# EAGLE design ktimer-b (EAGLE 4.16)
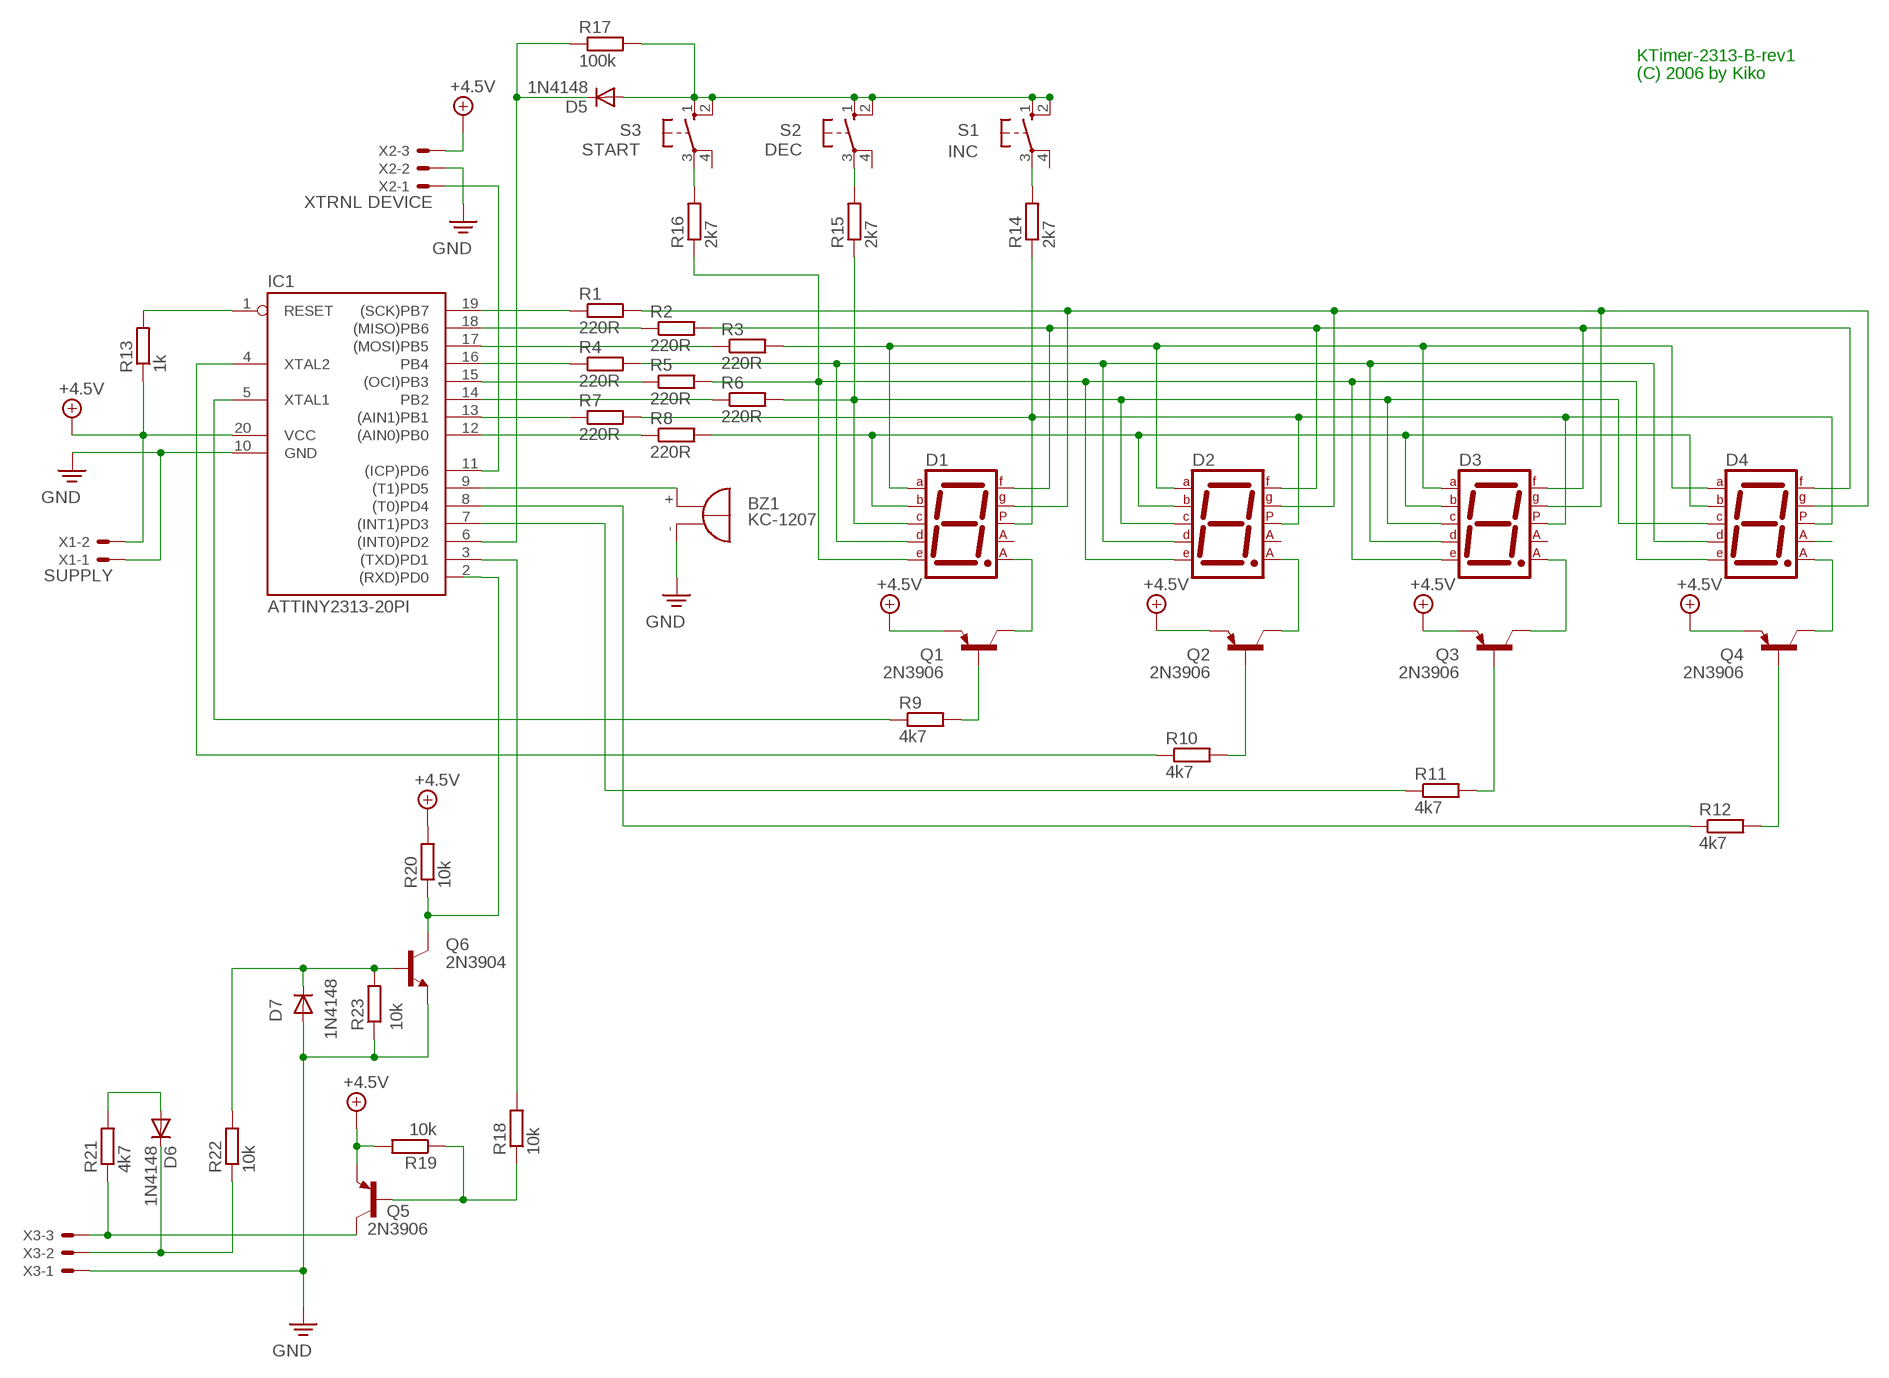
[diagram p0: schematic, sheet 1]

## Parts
BZ1  KC-1207  F/QMBIII  [F/QMBIII]
D1  7SEG-CA  [7SEG-13]
D2  7SEG-CA  [7SEG-13]
D3  7SEG-CA  [7SEG-13]
D4  7SEG-CA  [7SEG-13]
D5  1N4148  BAT81  [DO34-7]
D6  1N4148  BAT81  [DO34-7]
D7  1N4148  BAT81  [DO34-7]
IC1  ATTINY2313-20PI  AT90S2313P  [DIL20]
Q1  2N3906  [TO92]
Q2  2N3906  [TO92]
Q3  2N3906  [TO92]
Q4  2N3906  [TO92]
Q5  2N3906  [TO92]
Q6  2N3904  [TO92]
R1  220R  R-EU_0204/7  [0204/7]
R2  220R  R-EU_0204/7  [0204/7]
R3  220R  R-EU_0204/7  [0204/7]
R4  220R  R-EU_0204/7  [0204/7]
R5  220R  R-EU_0204/7  [0204/7]
R6  220R  R-EU_0204/7  [0204/7]
R7  220R  R-EU_0204/7  [0204/7]
R8  220R  R-EU_0204/7  [0204/7]
R9  4k7  R-EU_0204/7  [0204/7]
R10  4k7  R-EU_0204/7  [0204/7]
R11  4k7  R-EU_0204/7  [0204/7]
R12  4k7  R-EU_0204/7  [0204/7]
R13  1k  R-EU_0204/7  [0204/7]
R14  2k7  R-EU_0204/7  [0204/7]
R15  2k7  R-EU_0204/7  [0204/7]
R16  2k7  R-EU_0204/7  [0204/7]
R17  100k  R-EU_0204/7  [0204/7]
R18  10k  R-EU_0207/2V  [0207/2V]
R19  10k  R-EU_0207/2V  [0207/2V]
R20  10k  R-EU_0207/2V  [0207/2V]
R21  4k7  R-EU_0207/2V  [0207/2V]
R22  10k  R-EU_0207/2V  [0207/2V]
R23  10k  R-EU_0207/2V  [0207/2V]
S1  INC  40-XX  [B3F-40XX]
S2  DEC  40-XX  [B3F-40XX]
S3  START  40-XX  [B3F-40XX]
X1  SUPPLY  22-23-2021  [22-23-2021]
X2  XTRNL DEVICE  22-23-2031  [22-23-2031]
X3  22-23-2031  [22-23-2031]

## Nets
+5V: IC1.20(VCC) Q1.3(E) Q2.3(E) Q3.3(E) Q4.3(E) Q5.3(E) R13.1 R19.2 R20.2 X1.2 X2.3 ; supply symbol labelled +4.5V
GND: BZ1.-(+) IC1.10(GND) X1.1 X2.2
N$1: D1.10(G) D2.10(G) D3.10(G) D4.10(G) R1.2
N$2: D1.9(F) D2.9(F) D3.9(F) D4.9(F) R2.2
N$3: D1.7(A) D2.7(A) D3.7(A) D4.7(A) R3.2
N$4: D1.2(D) D2.2(D) D3.2(D) D4.2(D) R4.2
N$5: D1.1(E) D2.1(E) D3.1(E) D4.1(E) R5.2 R16.1
N$6: D1.4(C) D2.4(C) D3.4(C) D4.4(C) R6.2 R15.1
N$7: D1.5(DP) D2.5(DP) D3.5(DP) D4.5(DP) R7.2 R14.1
N$8: D1.6(B) D2.6(B) D3.6(B) D4.6(B) R8.2
N$9: IC1.19((SCK)PB7) R1.1
N$10: IC1.18((MISO)PB6) R2.1
N$11: IC1.17((MOSI)PB5) R3.1
N$12: IC1.16(PB4) R4.1
N$13: IC1.15((OCI)PB3) R5.1
N$14: IC1.14(PB2) R6.1
N$15: IC1.13((AIN1)PB1) R7.1
N$16: IC1.12((AIN0)PB0) R8.1
N$17: Q1.2(B) R9.2
N$18: IC1.5(XTAL1) R9.1
N$19: D1.8(CA2) Q1.1(C)
N$20: D2.8(CA2) Q2.1(C)
N$21: D3.8(CA2) Q3.1(C)
N$22: D4.3(CA1)
N$23: Q2.2(B) R10.2
N$24: IC1.4(XTAL2) R10.1
N$25: Q3.2(B) R11.2
N$26: Q4.2(B) R12.2
N$27: IC1.7((INT1)PD3) R11.1
N$28: IC1.8((T0)PD4) R12.1
N$29: IC1.1(RESET) R13.2
N$30: BZ1.+(-) IC1.9((T1)PD5)
N$31: R14.2 S1.3(P)
N$32: R15.2 S2.3(P)
N$33: R16.2 S3.3(P)
N$34: D5.C IC1.6((INT0)PD2) R17.1
N$35: D5.A R17.2 S1.1(S) S1.2(S1) S2.1(S) S2.2(S1) S3.1(S) S3.2(S1)
N$36: D4.8(CA2) Q4.1(C)
N$37: IC1.11((ICP)PD6) X2.1
N$38: IC1.3((TXD)PD1) R18.2
N$39: Q5.2(B) R18.1 R19.1
N$42: Q5.1(C) R21.1 X3.3
N$43: IC1.2((RXD)PD0) Q6.1(C) R20.1
N$44: D6.C R22.1 X3.2
N$45: D7.C Q6.2(B) R22.2 R23.2
N$46: D6.A R21.2
PE: D7.A Q6.3(E) R23.1 X3.1 ; supply symbol labelled GND
Unconnected: D1.3(CA1) D2.3(CA1) D3.3(CA1) S1.4(P1) S2.4(P1) S3.4(P1)

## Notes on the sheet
- KTimer-2313-B-rev1
- (C) 2006 by Kiko

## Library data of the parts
BZ1 = buzzer:F/QMBIII: BUZZER
D1-D4 = special:7SEG-CA: 7-segment DISPLAY single anode, 13 mm
D5-D7 = diode:BAT81: DIODE
IC1 = atmel2:AT90S2313: MICROCONTROLLER 2 Kbytes FLASH 128 bytes SRAM 128 bytes EEPROM UART
Q1-Q5 = transistor-pnp:2N3906: PNP Transistor
Q6 = transistor-npn:2N3904: NPN Transistor
R1-R23 = rcl:R-EU_: RESISTOR, European symbol
S1-S3 = switch-omron:40-XX: OMRON SWITCH
X1 = con-molex:22-23-2021: .100" (2.54mm) Center Header - 2 Pin
X2 X3 = con-molex:22-23-2031: .100" (2.54mm) Center Header - 3 Pin

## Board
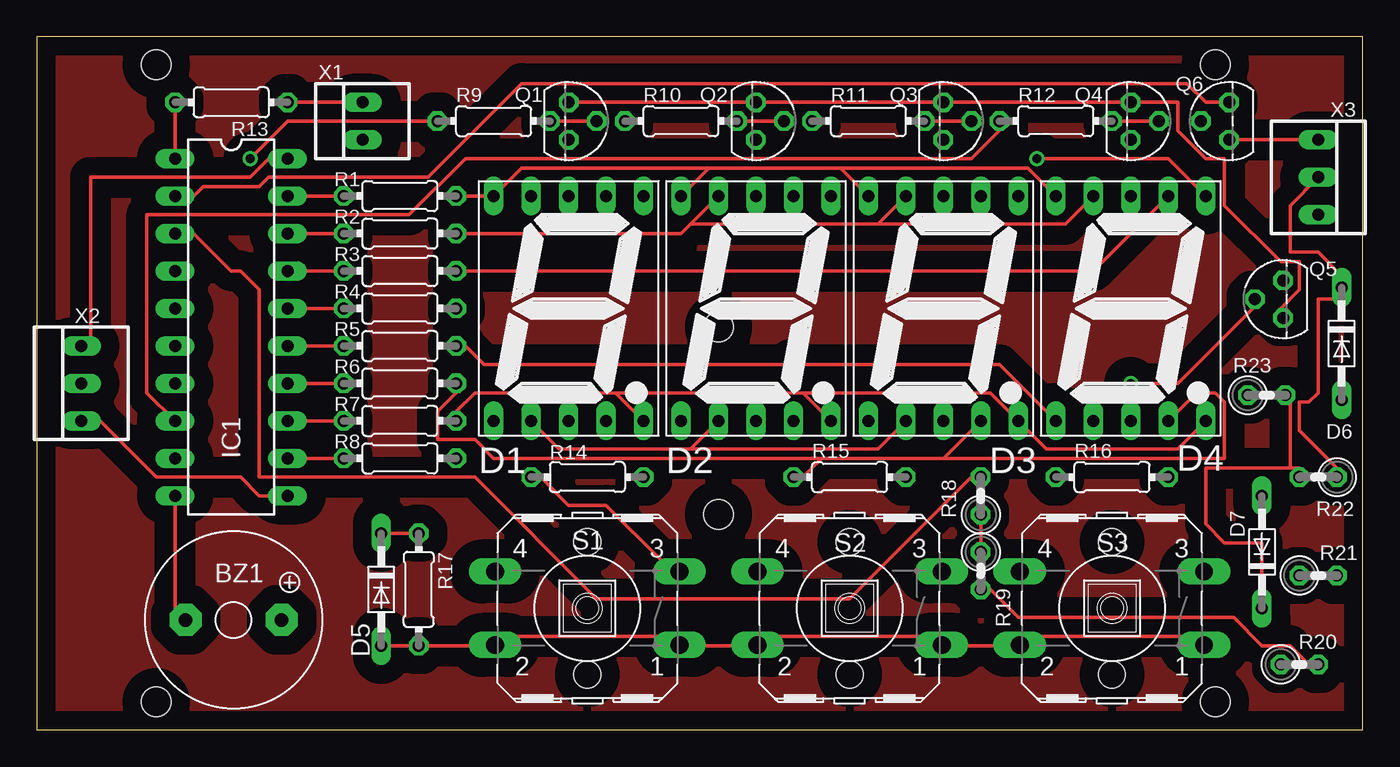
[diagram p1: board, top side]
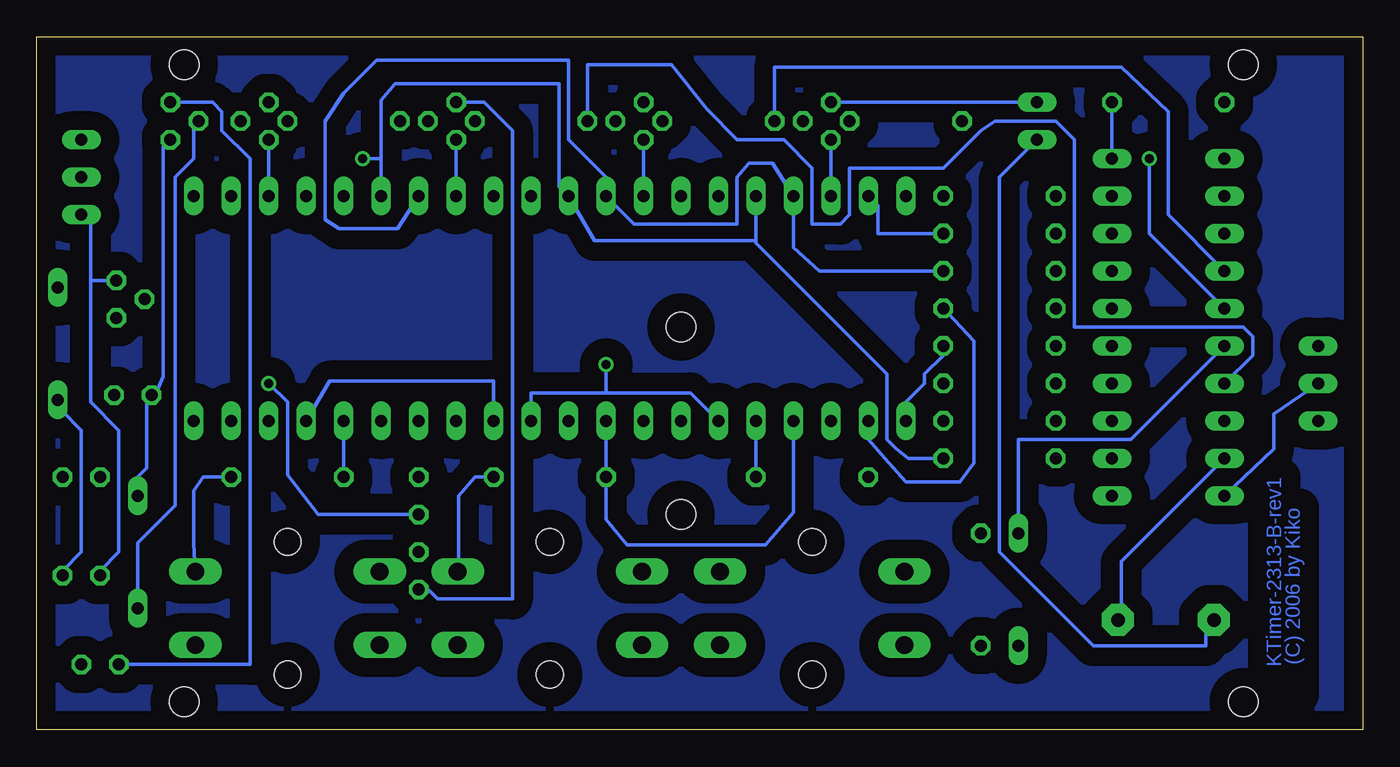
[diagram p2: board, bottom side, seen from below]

Size 89.84 x 46.98 mm. Coordinates in mm from the lower left corner, seen from the top.
Outline: 0,0 89.84,0 89.84,46.98 0,46.98 0,0
Copper layers (1*16): Top 0.035mm / dielectric 1.5mm / Bottom 0.035mm
Design rules "default": minimum track width 10mil, minimum drill 24mil, track to track 8mil, track to pad 8mil, pad to pad 8mil, via to via 8mil, smd to smd 8mil, copper to edge 40mil, drill to drill 8mil, minimum pad ring 10mil, minimum via ring 8mil, stop-mask expansion 4mil, vias tented up to drill 0mil, thermal gap 10mil
Holes 2 mm at 8.09,45.08 8.09,1.9 79.84,1.9 79.84,45.08 46.19,14.6 46.19,27.3

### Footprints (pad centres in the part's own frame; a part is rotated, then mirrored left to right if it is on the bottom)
F/QMBIII = drill 0.914 pad 2.159 octagon: + 3.251,0; - -3.251,0
7SEG-13 = drill 0.813 long: 1 -5.08,-7.62; 2 -2.54,-7.62; 3 0,-7.62; 4 2.54,-7.62; 5 5.08,-7.62; 6 5.08,7.62; 7 2.54,7.62; 8 0,7.62; 9 -2.54,7.62; 10 -5.08,7.62
DO34-7 = drill 0.813 long: A 3.81,0; C -3.81,0
DIL20 = drill 0.813 long: 1 -11.43,-3.81; 2 -8.89,-3.81; 3 -6.35,-3.81; 4 -3.81,-3.81; 5 -1.27,-3.81; 6 1.27,-3.81; 7 3.81,-3.81; 8 6.35,-3.81; 9 8.89,-3.81; 10 11.43,-3.81; 11 11.43,3.81; 12 8.89,3.81; 13 6.35,3.81; 14 3.81,3.81; 15 1.27,3.81; 16 -1.27,3.81; 17 -3.81,3.81; 18 -6.35,3.81; 19 -8.89,3.81; 20 -11.43,3.81
TO92 = drill 0.813 octagon: 1 1.27,0; 2 0,1.905; 3 -1.27,0
0204/7 = drill 0.813 octagon: 1 -3.81,0; 2 3.81,0
0207/2V = drill 0.813 octagon: 1 -1.27,0; 2 1.27,0
B3F-40XX = drill 1.194 long: 1 -6.248,2.489; 2 6.248,2.489; 3 -6.248,-2.489; 4 6.248,-2.489 | hole 1.803: 0,-4.496; 0,4.496
22-23-2021 = drill 0.813 long: 1 -1.27,0; 2 1.27,0
22-23-2031 = drill 0.813 long: 1 -2.54,0; 2 0,0; 3 2.54,0

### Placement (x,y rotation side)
BZ1  13.33,7.46 0 top
D1  36.03,28.57 0 top
D2  48.73,28.57 0 top
D3  61.43,28.57 0 top
D4  74.13,28.57 0 top
D5  23.33,9.52 270 top
D6  88.42,26.19 270 top
D7  83.02,12.06 90 top
IC1  13.17,27.3 270 top
Q1  36.03,41.27 270 top
Q2  48.73,41.27 270 top
Q3  61.43,41.27 270 top
Q4  74.13,41.27 270 top
Q5  84.45,29.2 90 top
Q6  80.8,41.27 90 top
R1  24.6,36.19 0 top
R2  24.6,33.65 0 top
R3  24.6,31.11 0 top
R4  24.6,28.57 0 top
R5  24.6,26.03 0 top
R6  24.6,23.49 0 top
R7  24.6,20.95 0 top
R8  24.6,18.41 0 top
R9  30.95,41.27 0 top
R10  43.65,41.27 0 top
R11  56.35,41.27 0 top
R12  69.05,41.27 0 top
R13  13.17,42.54 180 top
R14  37.3,17.14 180 top
R15  55.08,17.14 0 top
R16  72.86,17.14 0 top
R17  25.87,9.52 270 top
R18  63.97,15.87 90 top
R19  63.97,10.79 270 top
R20  85.56,4.44 0 top
R21  86.83,10.47 0 top
R22  86.83,17.14 180 top
R23  83.34,22.7 0 top
S1  37.3,8.25 180 top
S2  55.08,8.25 180 top
S3  72.86,8.25 180 top
X1  22.06,41.27 90 top
X2  3.01,23.49 90 top
X3  SERIAL  [22-23-2031]  86.83,37.46 270 top

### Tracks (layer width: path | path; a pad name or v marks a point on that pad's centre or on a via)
+5V
  Top 0.254: X2.3 3.65,26.66 3.65,37.46 14.44,37.46 15.71,38.73 IC1.20 | R13.1 X1.2 | R19.2 64.6,9.52 66.51,7.62 81.11,7.62 83.02,5.71 84.92,5.71 86.19,4.44 R20.2 | Q1.3 Q2.3 Q3.3 Q4.3 77.3,42.54 77.3,40.63 79.21,38.73 80.48,38.73 80.48,35.55 84.29,31.74 85.56,31.74 85.56,29.84 84.29,28.57 Q5.3
  Bottom 0.254: IC1.20 R13.1 | R19.2 63.33,9.52 62.7,8.88 57.62,8.88 57.62,40.63 59.53,42.54 Q3.3 | X1.2 Q1.3
GND
  Top 0.254: IC1.10 9.36,8.25 BZ1.-
  Bottom 0.254: X2.2 6.03,21.43 6.03,19.04 IC1.10 | X1.1 24.6,37.46 24.6,12.06 18.25,5.71 10.63,5.71 10.63,6.98 BZ1.-
N$1
  Top 0.254: R1.2 D1.10 32.86,38.09 45.56,38.09 | 45.56,38.09 54.44,38.09 | 45.56,38.09 D2.10 | 54.44,38.09 D3.10 | 54.44,38.09 67.14,38.09 D4.10
N$2
  Top 0.254: 44.28,34.28 43.65,33.65 R2.2 | 44.28,34.28 D2.9 | 44.28,34.28 56.98,34.28 | 56.98,34.28 D3.9 | 56.98,34.28 69.69,34.28 D4.9
  Bottom 0.254: R2.2 32.86,33.65 32.86,35.55 D1.9
N$3
  Top 0.254: D4.7 71.59,31.11 R3.2
  Bottom 0.254: R3.2 36.82,31.11 38.57,32.7 D1.7 40,38.41 41.59,38.41 42.38,37.46 42.38,34.28 49.36,34.28 D2.7 51.27,37.46 53.81,40 53.81,45.4 66.83,45.4 69.05,43.17 70.32,41.27 70.32,34.6 69.37,33.97 65.4,33.97 D3.7
N$4
  Top 0.254: 44.28,19.04 35.39,19.04 D1.2 | 44.28,19.04 D2.2 | 44.28,19.04 56.98,19.04 D3.2
  Bottom 0.254: R4.2 28.09,28.25 26.35,26.35 26.35,18.09 27.3,16.82 30.95,16.82 32.38,18.41 33.49,19.68 D1.2 | D4.2 70,23.65 58.89,23.65 D3.2
N$5  (via drill 0.61)
  Top 0.254: D4.1 65.24,24.76 v51.27,24.76 30.32,24.76 29.04,26.03 R5.2
  Bottom 0.254: 51.27,22.86 56.35,22.86 D3.1 | 51.27,22.86 45.56,22.86 D2.1 | D4.1 R16.1 | D1.1 30.95,22.22 29.68,23.49 29.68,24.12 28.41,25.39 R5.2 | v51.27,24.76 51.27,22.86
N$6
  Top 0.254: 53.17,18.41 61.43,18.41 | 53.17,18.41 51.91,17.14 R15.1 | 61.43,18.41 D3.4 | 61.43,18.41 80.48,18.41 80.48,22.22 79.84,22.86 78.58,22.86 D4.4 | 53.17,18.41 30.95,18.41 29.68,19.68 27.14,19.68 27.14,21.59 28.41,22.86 R6.2
  Bottom 0.254: D2.4 R15.1 51.27,16.35 51.27,14.28 49.84,12.54 40.47,12.54 38.57,14.76 38.57,19.68 D1.4
N$7
  Top 0.254: 39.2,22.86 29.68,22.86 28.41,21.59 R7.2 | 39.2,22.86 D1.5 | 39.2,22.86 51.91,22.86 | 51.91,22.86 D2.5 | 51.91,22.86 64.6,22.86 D3.5 68.41,19.04 77.3,19.04 D4.5
  Bottom 0.254: D1.5 R14.1
N$8  (via drill 0.61)
  Top 0.254: v67.78,38.73 76.67,38.73 D4.6
  Bottom 0.254: 41.11,33.17 41.11,33.02 32.22,24.12 32.22,19.68 31.58,19.04 30.79,18.41 R8.2 | 41.11,33.17 D1.6 | 41.11,33.17 52.06,33.17 D2.6 54.44,36.83 54.44,43.81 65.56,43.81 66.51,42.7 66.51,38.73 | 66.51,38.73 D3.6 | 66.51,38.73 v67.78,38.73
N$9
  Top 0.254: IC1.19 R1.1
N$10
  Top 0.254: IC1.18 R2.1
N$11
  Top 0.254: IC1.17 R3.1
N$12
  Top 0.254: IC1.16 R4.1
N$13
  Top 0.254: IC1.15 R5.1
N$14
  Top 0.254: IC1.14 R6.1
N$15
  Top 0.254: IC1.13 R7.1
N$16
  Top 0.254: IC1.12 R8.1
N$17
  Top 0.254: R9.2 Q1.2
N$18  (via drill 0.61)
  Top 0.254: v14.44,38.73 16.98,41.27 R9.1
  Bottom 0.254: v14.44,38.73 14.44,33.65 IC1.5
N$19
  Bottom 0.254: D1.8 Q1.1
N$20
  Bottom 0.254: D2.8 Q2.1
N$21
  Bottom 0.254: D3.8 Q3.1
N$23
  Top 0.254: R10.2 Q2.2
N$24
  Bottom 0.254: IC1.4 13.17,34.92 13.17,41.91 16.34,44.92 39.84,44.92 R10.1
N$25
  Top 0.254: R11.2 Q3.2
N$26
  Top 0.254: R12.2 Q4.2
N$27
  Bottom 0.254: IC1.7 7.46,25.39 7.46,26.66 8.09,27.3 19.52,27.3 19.52,40 20.79,41.27 24.92,41.27 25.87,40.63 28.41,38.09 34.76,38.09 34.76,34.92 35.39,34.28 37.3,34.28 37.3,38.09 39.2,40 42.38,40 44.44,42.06 46.83,45.08 52.54,45.08 R11.1
N$28
  Top 0.254: IC1.8 7.46,22.86 7.46,34.92 25.23,34.92 29.04,38.73 63.33,38.73 65.24,40.63 R12.1
N$29
  Top 0.254: IC1.1 R13.2
N$30
  Bottom 0.254: IC1.9 16.34,11.42 16.34,8.25 BZ1.+
N$31
  Top 0.254: R14.2 34.12,17.14 36.03,15.23 38.57,15.23 42.38,11.42 S1.3
N$32
  Bottom 0.254: R15.2 60.16,17.14 61.27,15.87 61.27,11.42 S2.3
N$33
  Bottom 0.254: R16.2 78.58,17.14 79.21,16.19 79.21,12.7 S3.3
N$34
  Top 0.254: D5.C R17.1
  Bottom 0.254: IC1.6 15.71,19.68 23.33,19.68 D5.C
N$35
  Top 0.254: S3.1 77.94,6.35 67.78,6.35 S3.2 65.24,5.71 62.7,5.71 S2.1 60.16,6.35 50,6.35 S2.2 47.46,5.71 44.92,5.71 S1.1 42.38,6.35 32.22,6.35 S1.2 29.68,5.71 R17.2 D5.A
N$36
  Bottom 0.254: D4.8 Q4.1
N$37
  Top 0.254: X2.1 4.28,20.95 8.09,17.14 13.8,17.14 15.07,15.87 IC1.11
N$38
  Top 0.254: IC1.3 10.63,33.65 13.17,31.11 13.8,31.11 15.07,29.84 15.07,17.14 29.68,17.14 37.94,8.88 55.08,8.88 63.33,17.14 R18.2
N$39  (via drill 0.61)
  Top 0.254: R19.1 R18.1 | v74.13,23.49 77.3,23.49 82.38,28.57 Q5.2
  Bottom 0.254: v74.13,23.49 72.86,22.22 72.86,17.3 70.8,14.6 R18.1
N$42
  Bottom 0.254: 86.19,30.47 86.19,34.28 X3.3 | 86.19,30.47 86.19,22.22 84.29,20.31 84.29,12.06 85.56,10.79 R21.1 | 86.19,30.47 Q5.1
N$43
  Top 0.254: IC1.2 10.63,36.19 11.27,36.83 15.07,36.83 15.71,37.46 26.5,37.46 32.86,43.81 77.94,43.81 79.21,42.54 Q6.1
  Bottom 0.254: R20.1 75.4,4.44 75.4,38.73 77.3,40.63 77.3,41.91 77.94,42.54 Q6.1
N$44
  Top 0.254: R22.1 88.1,17.77 85.56,20.31 85.56,22.22 86.19,22.22 86.83,22.86 86.83,29.2 88.1,29.2 D6.C 88.1,31.11 86.83,32.38 84.92,32.38 84.92,35.55 X3.2
N$45
  Top 0.254: 84.92,17.77 85.56,17.77 R22.2 | 84.92,17.77 79.21,17.77 79.21,13.96 80.48,12.7 83.02,12.7 D7.C | 84.92,17.77 84.92,22.22 R23.2
  Bottom 0.254: Q6.2 79.21,41.27 79.21,38.73 80.48,37.46 80.48,15.23 83.02,12.7 D7.C
N$46
  Bottom 0.254: R21.2 88.1,10.79 86.83,12.06 86.83,20.31 88.1,21.59 D6.A
N$47
  pour Bottom (isolate 1.27, no thermals): 0.47,46.35 89.37,46.35 89.37,0.63 0.47,0.63
N$48
  pour Top (isolate 1.27, no thermals): 0.47,46.35 89.37,46.35 89.37,0.63 0.47,0.63
PE
  Top 0.254: Q6.3 X3.1
  Bottom 0.254: D7.A 83.02,17.14 82.38,17.77 82.38,22.22 R23.1 81.75,22.86 81.27,23.97 81.27,39.52 Q6.3

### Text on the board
Bottom: KTimer-2313-B-rev1 | (C) 2006 by Kiko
